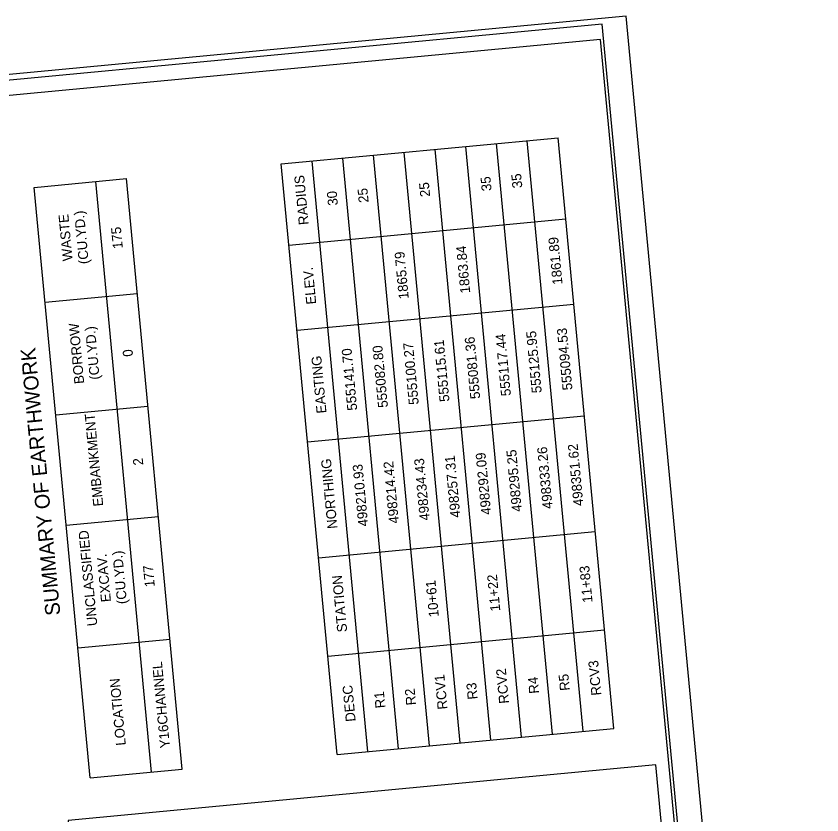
# Model space of a CAD drawing. Extents: x 554635 to 555260, y 497951 to 498841.
# Drawn here: x 554933.4 to 555259.5, y 498517.4 to 498840.6 of the extents above; entities that cross this region are included whole.
import ezdxf

# ---------------------------------------------------------------- set-up
doc = ezdxf.new("R2010")
doc.units = 0
for name, color, linetype in [('Prop Plan Preparation Table Ditch Data CELL', 7, 'Continuous'), ('Scratch_Level_0', 7, 'Continuous'), ('Sheet Layout Plan Border', 7, 'Continuous'), ('Sheet Plan CELL', 7, 'Continuous'), ('Sheet Plot Border Inside CELL', 7, 'Continuous'), ('Sheet Plot Border Outside CELL', 7, 'Continuous')]:
    doc.layers.add(name, color=color, linetype=linetype)

msp = doc.modelspace()

# ---------------------------------------------------------------- linework, layer by layer
at = {"layer": 'Prop Plan Preparation Table Ditch Data CELL'}
for p, q in [((555040.73, 498780.74), (555152.74, 498791.33)), ((555175.32, 498552.4), (555152.74, 498791.33)), ((555137.99, 498548.87), (555115.4, 498787.8)), ((555150.44, 498550.05), (555127.85, 498788.98)), ((555162.88, 498551.22), (555140.29, 498790.16)), ((555100.66, 498545.34), (555078.07, 498784.27)), ((555113.1, 498546.52), (555090.51, 498785.45)), ((555125.55, 498547.69), (555102.96, 498786.63)), ((555075.77, 498542.99), (555053.18, 498781.92)), ((555088.21, 498544.16), (555065.62, 498783.1)), ((555000.66, 498535.89), (554978.07, 498774.82)), ((554988.22, 498534.71), (554965.63, 498773.64)), ((555043.83, 498747.95), (555155.84, 498758.54)), ((554945.13, 498724.81), (554982.46, 498728.34)), ((555047.1, 498713.45), (555159.1, 498724.04)), ((554949.44, 498679.26), (554986.77, 498682.79)), ((555051.36, 498668.31), (555163.37, 498678.9)), ((554953.66, 498634.56), (554991, 498638.09)), ((555055.79, 498621.46), (555167.79, 498632.04)), ((555059.56, 498581.63), (555171.56, 498592.22)), ((554958.35, 498584.94), (554995.69, 498588.47)), ((555063.32, 498541.81), (555175.32, 498552.4)), ((554963.33, 498532.36), (555000.66, 498535.89))]:
    msp.add_line(p, q, dxfattribs=at)
for points in [[(555063.32, 498541.81), (555040.73, 498780.74), (555152.74, 498791.33)], [(554963.33, 498532.36), (554940.74, 498771.29), (554978.07, 498774.82)]]:
    msp.add_lwpolyline(points, dxfattribs=at)
at = {"layer": 'Scratch_Level_0'}
msp.add_line((554940.74, 498771.29), (554978.07, 498774.82), dxfattribs=at)
at = {"layer": 'Sheet Layout Plan Border'}
msp.add_lwpolyline([(555232.94, 498108.76), (555192.39, 498537.63), (554954.42, 498515.13), (554994.97, 498086.26)], close=True, dxfattribs=at)
msp.add_lwpolyline([(555232.94, 498108.76), (555192.39, 498537.63), (554954.42, 498515.13), (554994.97, 498086.26)], close=True, dxfattribs=at)
at = {"layer": 'Sheet Plan CELL'}
msp.add_lwpolyline([(554647.23, 498781.63), (554717.82, 498034.95), (555240.49, 498084.36), (555169.9, 498831.04)], close=True, dxfattribs=at)
at = {"layer": 'Sheet Plot Border Inside CELL'}
msp.add_lwpolyline([(555248.96, 498008.08), (555170.55, 498837.37), (554645.4, 498787.73), (554723.81, 497958.43)], close=True, dxfattribs=at)
at = {"layer": 'Sheet Plot Border Outside CELL'}
msp.add_lwpolyline([(555259.53, 498002.55), (555180.3, 498840.56), (554635.23, 498789.03), (554714.46, 497951.01)], close=True, dxfattribs=at)

# ---------------------------------------------------------------- texts
at = {"layer": 'Prop Plan Preparation Table Ditch Data CELL'}
for s, height, p in [('RADIUS', 4, (555051.84, 498756.26)), ('35', 4, (555125.88, 498769.95)), ('35', 4, (555138.32, 498771.13)), ('25', 4, (555076.1, 498765.24)), ('25', 4, (555100.99, 498767.6)), ('30', 4, (555063.66, 498764.07)), ('(CU.YD.)', 4, (554962.85, 498740.42)), ('WASTE', 4, (554956.3, 498741.69)), ('175', 4, (554976.61, 498746.59)), ('1861.89', 4, (555154.57, 498732.12)), ('1865.79', 4, (555092.34, 498726.24)), ('1863.84', 4, (555117.23, 498728.59)), ('ELEV.', 4, (555054.88, 498724.11)), ('BORROW', 4, (554961, 498691.94)), ('(CU.YD.)', 4, (554967.27, 498693.65)), ('555125.95', 4, (555146.16, 498688.22)), ('555094.53', 4, (555158.61, 498689.39)), ('555115.61', 4, (555108.83, 498684.69)), ('555081.36', 4, (555121.27, 498685.86)), ('555117.44', 4, (555133.72, 498687.04)), ('SUMMARY OF EARTHWORK', 6, (554951.34, 498598.33)), ('0', 4, (554980.74, 498702.97)), ('555141.70', 4, (555071.49, 498681.16)), ('555082.80', 4, (555083.94, 498682.33)), ('555100.27', 4, (555096.38, 498683.51)), ('EASTING', 4, (555059.05, 498680)), ('EMBANKMENT', 4, (554968.67, 498642.4)), ('498351.62', 4, (555163.04, 498642.54)), ('498292.09', 4, (555125.7, 498639.01)), ('498295.25', 4, (555138.15, 498640.19)), ('498333.26', 4, (555150.59, 498641.36)), ('2', 4, (554984.89, 498659.01)), ('NORTHING', 4, (555063.46, 498633.34)), ('498214.42', 4, (555088.37, 498635.48)), ('498234.43', 4, (555100.81, 498636.66)), ('498257.31', 4, (555113.26, 498637.83)), ('498210.93', 4, (555075.92, 498634.3)), ('UNCLASSIFIED ', 4, (554966.29, 498593.97)), ('(CU.YD.)', 4, (554978.31, 498602.87)), ('EXCAV.', 4, (554971.8, 498603.66)), ('177', 4, (554989.55, 498609.73)), ('11+83', 4, (555166.73, 498603.45)), ('11+22', 4, (555129.4, 498599.92)), ('STATION', 4, (555067.42, 498591.48)), ('10+61', 4, (555104.51, 498597.57)), ('Y16CHANNEL', 4, (554995.71, 498544.62)), ('RCV3', 4, (555170.28, 498565.88)), ('RCV2', 4, (555132.93, 498562.59)), ('LOCATION', 4, (554977.82, 498545.62)), ('RCV1', 4, (555108.04, 498560.23)), ('R4', 4, (555145.1, 498566.62)), ('R5', 4, (555157.55, 498567.8)), ('DESC', 4, (555070.84, 498555.29)), ('R3', 4, (555120.21, 498564.27)), ('R1', 4, (555082.88, 498560.74)), ('R2', 4, (555095.32, 498561.92))]:
    msp.add_text(s, height=height, rotation=95.4008, dxfattribs=at).set_placement(p)

doc.saveas('drawing.dxf')
